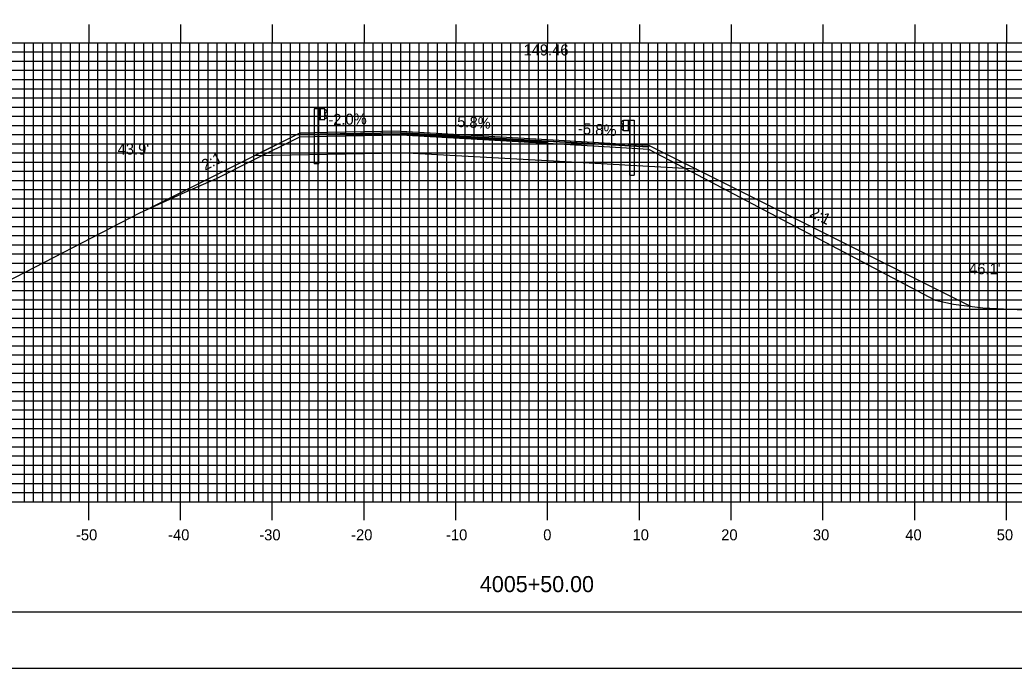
# Model space of a CAD drawing. Extents: x 851360 to 851703, y 364661 to 364881.
# Drawn here: x 851468.2 to 851576.6, y 364661.3 to 364731.9 of the extents above; entities that cross this region are included whole.
import ezdxf

# ---------------------------------------------------------------- set-up
doc = ezdxf.new("R2010")
doc.units = 0
for name, color, linetype in [('ANNOTATION', 7, 'Continuous'), ('BORDER', 7, 'Continuous'), ('D_Guardrail_Beam_Lt', 7, 'Continuous'), ('D_Guardrail_Beam_Rt', 7, 'Continuous'), ('D_Roadway_Centerline_Text', 7, 'Continuous'), ('D_Roadway_Edge_Shoulder', 7, 'Continuous'), ('D_Roadway_Edge_TW', 7, 'Continuous'), ('D_Roadway_Pavement', 7, 'Continuous'), ('D_Roadway_SlopeLines', 7, 'Continuous'), ('D_Roadway_SubGrade', 7, 'Continuous'), ('D_Text_Standard', 7, 'Continuous'), ('H_V ANNOTATION', 7, 'Continuous'), ('M_Roadway_Centerline', 7, 'Continuous'), ('MAJOR', 7, 'Continuous'), ('MINOR', 7, 'Continuous'), ('PLOT BOUNDARY', 7, 'Continuous'), ('S_Roadway_Centerline', 7, 'Continuous')]:
    doc.layers.add(name, color=color, linetype=linetype)

msp = doc.modelspace()

# ---------------------------------------------------------------- linework, layer by layer
at = {"layer": 'BORDER'}
msp.add_lwpolyline([(851376.13, 364667.37), (851696.13, 364667.37), (851696.13, 364877.37), (851376.13, 364877.37)], close=True, dxfattribs=at)
at = {"layer": 'D_Guardrail_Beam_Lt'}
for p, q in [((851500.3, 364722.19), (851500.3, 364716.19)), ((851500.77, 364722.19), (851500.3, 364722.19)), ((851501.46, 364722.19), (851500.77, 364722.19)), ((851500.77, 364722.19), (851500.77, 364721.02)), ((851500.83, 364722.19), (851500.83, 364721.02)), ((851500.94, 364722.19), (851500.94, 364721.02)), ((851501.46, 364721.02), (851501.46, 364722.19)), ((851501.46, 364722.1), (851501.53, 364722.09)), ((851501.55, 364722.08), (851501.69, 364721.98)), ((851500.77, 364721.02), (851501.46, 364721.02)), ((851500.79, 364716.19), (851500.79, 364721.02)), ((851501.46, 364721.64), (851501.46, 364721.57)), ((851501.53, 364721.12), (851501.46, 364721.1)), ((851501.69, 364721.84), (851501.5, 364721.7)), ((851501.5, 364721.5), (851501.69, 364721.37)), ((851501.69, 364721.22), (851501.55, 364721.12)), ((851500.79, 364716.19), (851500.3, 364716.19))]:
    msp.add_line(p, q, dxfattribs=at)
for centre, major_axis, start_param, end_param in [((851501.52, 364722.05), (0.0417, 0), 0.959931, 1.376053), ((851501.54, 364721.64), (-0.0789, 0), 5.323254, 6.283185), ((851501.54, 364721.57), (-0.0789, 0), 6.283185, 7.243116), ((851501.52, 364721.16), (0.0417, 0), 4.907132, 5.323254), ((851501.64, 364721.91), (0.0877, 0), 5.323254, 7.243116), ((851501.64, 364721.3), (0.0877, 0), 5.323254, 7.243116)]:
    msp.add_ellipse(centre, major_axis=major_axis, ratio=0.995501, start_param=start_param, end_param=end_param, dxfattribs=at)
at = {"layer": 'D_Guardrail_Beam_Rt'}
for p, q in [((851534, 364720.95), (851534.69, 364720.95)), ((851534, 364719.79), (851534, 364720.95)), ((851534.52, 364720.95), (851534.52, 364719.79)), ((851534.62, 364720.95), (851534.62, 364719.79)), ((851534.69, 364720.95), (851535.16, 364720.95)), ((851534.69, 364720.95), (851534.69, 364719.79)), ((851535.16, 364720.95), (851535.16, 364714.95)), ((851533.91, 364720.85), (851533.77, 364720.75)), ((851533.77, 364720.61), (851533.96, 364720.47)), ((851533.96, 364720.27), (851533.77, 364720.13)), ((851533.77, 364719.99), (851533.91, 364719.89)), ((851534, 364720.87), (851533.93, 364720.86)), ((851533.93, 364719.88), (851534, 364719.87)), ((851534, 364720.41), (851534, 364720.34)), ((851534.69, 364719.79), (851534, 364719.79)), ((851534.67, 364714.95), (851534.67, 364719.79)), ((851534.67, 364714.95), (851535.16, 364714.95))]:
    msp.add_line(p, q, dxfattribs=at)
for centre, major_axis, start_param, end_param in [((851533.82, 364720.68), (-0.0877, 0), 5.323254, 7.243116), ((851533.82, 364720.06), (-0.0877, 0), 5.323254, 7.243116), ((851533.93, 364720.82), (-0.0417, 0), 4.907132, 5.323254), ((851533.93, 364719.93), (-0.0417, 0), 0.959931, 1.376053), ((851533.92, 364720.41), (0.0789, 0), 0, 0.959931), ((851533.92, 364720.34), (0.0789, 0), 5.323254, 6.283185)]:
    msp.add_ellipse(centre, major_axis=major_axis, ratio=0.995501, start_param=start_param, end_param=end_param, dxfattribs=at)
at = {"layer": 'D_Roadway_Edge_Shoulder'}
for points in [[(851509.73, 364719.76), (851501.73, 364719.6), (851501.73, 364719.6), (851498.73, 364719.54), (851498.73, 364719.38), (851509.73, 364719.57)], [(851525.73, 364718.83), (851533.73, 364718.37), (851533.73, 364718.37), (851536.73, 364718.2), (851536.73, 364718.03), (851525.73, 364718.67)]]:
    msp.add_lwpolyline(points, close=True, dxfattribs=at)
at = {"layer": 'D_Roadway_Edge_TW'}
msp.add_lwpolyline([(851509.73, 364719.76), (851525.73, 364718.83), (851525.73, 364718.67), (851509.73, 364719.57)], close=True, dxfattribs=at)
at = {"layer": 'D_Roadway_Pavement'}
msp.add_lwpolyline([(851509.73, 364719.57), (851525.73, 364718.67), (851525.73, 364718.5), (851509.73, 364719.4)], close=True, dxfattribs=at)
for points in [[(851509.73, 364719.57), (851509.73, 364719.4)], [(851525.73, 364718.67), (851525.73, 364718.5)], [(851525.73, 364718.67), (851525.73, 364718.5)], [(851525.73, 364718.67), (851525.73, 364718.5)]]:
    msp.add_lwpolyline(points, dxfattribs=at)
at = {"layer": 'D_Roadway_SlopeLines'}
for points in [[(851498.73, 364719.54), (851481.79, 364711.07)], [(851536.73, 364718.2), (851571.79, 364700.67)]]:
    msp.add_lwpolyline(points, dxfattribs=at)
at = {"layer": 'D_Roadway_SubGrade'}
for points in [[(851509.73, 364719.4), (851509.73, 364719.57), (851498.73, 364719.38), (851498.73, 364719.54), (851493.81, 364717.08), (851509.73, 364717.4)], [(851509.73, 364719.4), (851525.73, 364718.5), (851525.73, 364716.5), (851509.73, 364717.4)], [(851525.73, 364718.5), (851525.73, 364718.67), (851536.73, 364718.03), (851536.73, 364718.2), (851541.94, 364715.59), (851525.73, 364716.5)]]:
    msp.add_lwpolyline(points, close=True, dxfattribs=at)
at = {"layer": 'MAJOR'}
for p, q in [((851475.73, 364731.37), (851475.73, 364729.37)), ((851485.73, 364731.37), (851485.73, 364729.37)), ((851495.73, 364731.37), (851495.73, 364729.37)), ((851505.73, 364731.37), (851505.73, 364729.37)), ((851515.73, 364731.37), (851515.73, 364729.37)), ((851525.73, 364731.37), (851525.73, 364729.37)), ((851535.73, 364731.37), (851535.73, 364729.37)), ((851545.73, 364731.37), (851545.73, 364729.37)), ((851555.73, 364731.37), (851555.73, 364729.37)), ((851565.73, 364731.37), (851565.73, 364729.37)), ((851575.73, 364731.37), (851575.73, 364729.37)), ((851385.73, 364729.37), (851665.73, 364729.37)), ((851385.73, 364729.37), (851665.73, 364729.37)), ((851475.73, 364679.37), (851475.73, 364729.37)), ((851485.73, 364679.37), (851485.73, 364729.37)), ((851495.73, 364679.37), (851495.73, 364729.37)), ((851505.73, 364679.37), (851505.73, 364729.37)), ((851515.73, 364679.37), (851515.73, 364729.37)), ((851525.73, 364679.37), (851525.73, 364729.37)), ((851535.73, 364679.37), (851535.73, 364729.37)), ((851545.73, 364679.37), (851545.73, 364729.37)), ((851555.73, 364679.37), (851555.73, 364729.37)), ((851565.73, 364679.37), (851565.73, 364729.37)), ((851575.73, 364679.37), (851575.73, 364729.37)), ((851385.73, 364724.37), (851665.73, 364724.37)), ((851385.73, 364719.37), (851665.73, 364719.37)), ((851385.73, 364714.37), (851665.73, 364714.37)), ((851385.73, 364709.37), (851665.73, 364709.37)), ((851385.73, 364704.37), (851665.73, 364704.37)), ((851385.73, 364699.37), (851665.73, 364699.37)), ((851385.73, 364694.37), (851665.73, 364694.37)), ((851385.73, 364689.37), (851665.73, 364689.37)), ((851385.73, 364684.37), (851665.73, 364684.37)), ((851385.73, 364679.37), (851665.73, 364679.37)), ((851385.73, 364679.37), (851665.73, 364679.37)), ((851475.73, 364677.37), (851475.73, 364679.37)), ((851485.73, 364677.37), (851485.73, 364679.37)), ((851495.73, 364677.37), (851495.73, 364679.37)), ((851505.73, 364677.37), (851505.73, 364679.37)), ((851515.73, 364677.37), (851515.73, 364679.37)), ((851525.73, 364677.37), (851525.73, 364679.37)), ((851535.73, 364677.37), (851535.73, 364679.37)), ((851545.73, 364677.37), (851545.73, 364679.37)), ((851555.73, 364677.37), (851555.73, 364679.37)), ((851565.73, 364677.37), (851565.73, 364679.37)), ((851575.73, 364677.37), (851575.73, 364679.37))]:
    msp.add_line(p, q, dxfattribs=at)
at = {"layer": 'MINOR'}
for p, q in [((851468.73, 364679.37), (851468.73, 364729.37)), ((851469.73, 364679.37), (851469.73, 364729.37)), ((851470.73, 364679.37), (851470.73, 364729.37)), ((851471.73, 364679.37), (851471.73, 364729.37)), ((851472.73, 364679.37), (851472.73, 364729.37)), ((851473.73, 364679.37), (851473.73, 364729.37)), ((851474.73, 364679.37), (851474.73, 364729.37)), ((851476.73, 364679.37), (851476.73, 364729.37)), ((851477.73, 364679.37), (851477.73, 364729.37)), ((851478.73, 364679.37), (851478.73, 364729.37)), ((851479.73, 364679.37), (851479.73, 364729.37)), ((851480.73, 364679.37), (851480.73, 364729.37)), ((851481.73, 364679.37), (851481.73, 364729.37)), ((851482.73, 364679.37), (851482.73, 364729.37)), ((851483.73, 364679.37), (851483.73, 364729.37)), ((851484.73, 364679.37), (851484.73, 364729.37)), ((851486.73, 364679.37), (851486.73, 364729.37)), ((851487.73, 364679.37), (851487.73, 364729.37)), ((851488.73, 364679.37), (851488.73, 364729.37)), ((851489.73, 364679.37), (851489.73, 364729.37)), ((851490.73, 364679.37), (851490.73, 364729.37)), ((851491.73, 364679.37), (851491.73, 364729.37)), ((851492.73, 364679.37), (851492.73, 364729.37)), ((851493.73, 364679.37), (851493.73, 364729.37)), ((851494.73, 364679.37), (851494.73, 364729.37)), ((851496.73, 364679.37), (851496.73, 364729.37)), ((851497.73, 364679.37), (851497.73, 364729.37)), ((851498.73, 364679.37), (851498.73, 364729.37)), ((851499.73, 364679.37), (851499.73, 364729.37)), ((851500.73, 364679.37), (851500.73, 364729.37)), ((851501.73, 364679.37), (851501.73, 364729.37)), ((851502.73, 364679.37), (851502.73, 364729.37)), ((851503.73, 364679.37), (851503.73, 364729.37)), ((851504.73, 364679.37), (851504.73, 364729.37)), ((851506.73, 364679.37), (851506.73, 364729.37)), ((851507.73, 364679.37), (851507.73, 364729.37)), ((851508.73, 364679.37), (851508.73, 364729.37)), ((851509.73, 364679.37), (851509.73, 364729.37)), ((851510.73, 364679.37), (851510.73, 364729.37)), ((851511.73, 364679.37), (851511.73, 364729.37)), ((851512.73, 364679.37), (851512.73, 364729.37)), ((851513.73, 364679.37), (851513.73, 364729.37)), ((851514.73, 364679.37), (851514.73, 364729.37)), ((851516.73, 364679.37), (851516.73, 364729.37)), ((851517.73, 364679.37), (851517.73, 364729.37)), ((851518.73, 364679.37), (851518.73, 364729.37)), ((851519.73, 364679.37), (851519.73, 364729.37)), ((851520.73, 364679.37), (851520.73, 364729.37)), ((851521.73, 364679.37), (851521.73, 364729.37)), ((851522.73, 364679.37), (851522.73, 364729.37)), ((851523.73, 364679.37), (851523.73, 364729.37)), ((851524.73, 364679.37), (851524.73, 364729.37)), ((851526.73, 364679.37), (851526.73, 364729.37)), ((851527.73, 364679.37), (851527.73, 364729.37)), ((851528.73, 364679.37), (851528.73, 364729.37)), ((851529.73, 364679.37), (851529.73, 364729.37)), ((851530.73, 364679.37), (851530.73, 364729.37)), ((851531.73, 364679.37), (851531.73, 364729.37)), ((851532.73, 364679.37), (851532.73, 364729.37)), ((851533.73, 364679.37), (851533.73, 364729.37)), ((851534.73, 364679.37), (851534.73, 364729.37)), ((851536.73, 364679.37), (851536.73, 364729.37)), ((851537.73, 364679.37), (851537.73, 364729.37)), ((851538.73, 364679.37), (851538.73, 364729.37)), ((851539.73, 364679.37), (851539.73, 364729.37)), ((851540.73, 364679.37), (851540.73, 364729.37)), ((851541.73, 364679.37), (851541.73, 364729.37)), ((851542.73, 364679.37), (851542.73, 364729.37)), ((851543.73, 364679.37), (851543.73, 364729.37)), ((851544.73, 364679.37), (851544.73, 364729.37)), ((851546.73, 364679.37), (851546.73, 364729.37)), ((851547.73, 364679.37), (851547.73, 364729.37)), ((851548.73, 364679.37), (851548.73, 364729.37)), ((851549.73, 364679.37), (851549.73, 364729.37)), ((851550.73, 364679.37), (851550.73, 364729.37)), ((851551.73, 364679.37), (851551.73, 364729.37)), ((851552.73, 364679.37), (851552.73, 364729.37)), ((851553.73, 364679.37), (851553.73, 364729.37)), ((851554.73, 364679.37), (851554.73, 364729.37)), ((851556.73, 364679.37), (851556.73, 364729.37)), ((851557.73, 364679.37), (851557.73, 364729.37)), ((851558.73, 364679.37), (851558.73, 364729.37)), ((851559.73, 364679.37), (851559.73, 364729.37)), ((851560.73, 364679.37), (851560.73, 364729.37)), ((851561.73, 364679.37), (851561.73, 364729.37)), ((851562.73, 364679.37), (851562.73, 364729.37)), ((851563.73, 364679.37), (851563.73, 364729.37)), ((851564.73, 364679.37), (851564.73, 364729.37)), ((851566.73, 364679.37), (851566.73, 364729.37)), ((851567.73, 364679.37), (851567.73, 364729.37)), ((851568.73, 364679.37), (851568.73, 364729.37)), ((851569.73, 364679.37), (851569.73, 364729.37)), ((851570.73, 364679.37), (851570.73, 364729.37)), ((851571.73, 364679.37), (851571.73, 364729.37)), ((851572.73, 364679.37), (851572.73, 364729.37)), ((851573.73, 364679.37), (851573.73, 364729.37)), ((851574.73, 364679.37), (851574.73, 364729.37)), ((851385.73, 364728.37), (851665.73, 364728.37)), ((851385.73, 364727.37), (851665.73, 364727.37)), ((851385.73, 364726.37), (851665.73, 364726.37)), ((851385.73, 364725.37), (851665.73, 364725.37)), ((851385.73, 364723.37), (851665.73, 364723.37)), ((851385.73, 364722.37), (851665.73, 364722.37)), ((851385.73, 364721.37), (851665.73, 364721.37)), ((851385.73, 364720.37), (851665.73, 364720.37)), ((851385.73, 364718.37), (851665.73, 364718.37)), ((851385.73, 364717.37), (851665.73, 364717.37)), ((851385.73, 364716.37), (851665.73, 364716.37)), ((851385.73, 364715.37), (851665.73, 364715.37)), ((851385.73, 364713.37), (851665.73, 364713.37)), ((851385.73, 364712.37), (851665.73, 364712.37)), ((851385.73, 364711.37), (851665.73, 364711.37)), ((851385.73, 364710.37), (851665.73, 364710.37)), ((851385.73, 364708.37), (851665.73, 364708.37)), ((851385.73, 364707.37), (851665.73, 364707.37)), ((851385.73, 364706.37), (851665.73, 364706.37)), ((851385.73, 364705.37), (851665.73, 364705.37)), ((851385.73, 364703.37), (851665.73, 364703.37)), ((851385.73, 364702.37), (851665.73, 364702.37)), ((851385.73, 364701.37), (851665.73, 364701.37)), ((851385.73, 364700.37), (851665.73, 364700.37)), ((851385.73, 364698.37), (851665.73, 364698.37)), ((851385.73, 364697.37), (851665.73, 364697.37)), ((851385.73, 364696.37), (851665.73, 364696.37)), ((851385.73, 364695.37), (851665.73, 364695.37)), ((851385.73, 364693.37), (851665.73, 364693.37)), ((851385.73, 364692.37), (851665.73, 364692.37)), ((851385.73, 364691.37), (851665.73, 364691.37)), ((851385.73, 364690.37), (851665.73, 364690.37)), ((851385.73, 364688.37), (851665.73, 364688.37)), ((851385.73, 364687.37), (851665.73, 364687.37)), ((851385.73, 364686.37), (851665.73, 364686.37)), ((851385.73, 364685.37), (851665.73, 364685.37)), ((851385.73, 364683.37), (851665.73, 364683.37)), ((851385.73, 364682.37), (851665.73, 364682.37)), ((851385.73, 364681.37), (851665.73, 364681.37)), ((851385.73, 364680.37), (851665.73, 364680.37))]:
    msp.add_line(p, q, dxfattribs=at)
at = {"layer": 'PLOT BOUNDARY'}
msp.add_lwpolyline([(851359.94, 364661.25), (851699.94, 364661.25), (851699.94, 364881.25), (851359.94, 364881.25)], close=True, dxfattribs=at)
at = {"layer": 'S_Roadway_Centerline'}
for points in [[(851489.65, 364714.59), (851493.52, 364716.53), (851498.73, 364719.13), (851501.73, 364719.19), (851509.73, 364719.35), (851525.73, 364718.42), (851533.73, 364717.96), (851536.73, 364717.78), (851542.07, 364714.97), (851567.97, 364701.34)], [(851385.73, 364688.72), (851388.91, 364688.93), (851400.08, 364689.25), (851405.67, 364689.62), (851416.25, 364690.29), (851430.53, 364691.53), (851433.06, 364691.66), (851448.42, 364694.67), (851448.62, 364694.71), (851464.4, 364702.17), (851465.67, 364702.79), (851481.28, 364710.84), (851486.23, 364713.08), (851489.65, 364714.59)], [(851567.97, 364701.34), (851569.96, 364700.89), (851573.14, 364700.5), (851579.13, 364700.2), (851581, 364700.11), (851596.8, 364701.03), (851598.31, 364701.08), (851613.16, 364702.25), (851613.88, 364702.3), (851614.56, 364702.29), (851630.83, 364702.08), (851631.08, 364702.08), (851640.65, 364703.15), (851647.46, 364703.83), (851659.92, 364704.09), (851663.96, 364704.22), (851665.73, 364704.47)]]:
    msp.add_lwpolyline(points, dxfattribs=at)

# ---------------------------------------------------------------- texts
at = {"layer": 'ANNOTATION'}
for s, rotation, p in [('-2.0%', 1.1458, (851501.84, 364720.4)), ('5.8%', 356.6806, (851515.84, 364720.21)), ('-5.8%', 356.6806, (851529.02, 364719.45)), ('2:1', 26.5651, (851488.4, 364715.42)), ('2:1', 333.4349, (851554.19, 364710.5))]:
    msp.add_text(s, height=1.2, rotation=rotation, dxfattribs=at).set_placement(p)
at = {"layer": 'D_Roadway_Centerline_Text'}
msp.add_text('149.46', height=1.2, dxfattribs=at).set_placement((851523.1, 364727.99))
at = {"layer": 'D_Text_Standard'}
for s, p in [("43.9'", (851478.88, 364717.2)), ("46.1'", (851571.65, 364704.16))]:
    msp.add_text(s, height=1.2, dxfattribs=at).set_placement(p)
at = {"layer": 'H_V ANNOTATION'}
for s, height, p in [('-50', 1.2, (851474.34, 364675.17)), ('-40', 1.2, (851484.38, 364675.17)), ('-30', 1.2, (851494.31, 364675.17)), ('-20', 1.2, (851504.32, 364675.17)), ('-10', 1.2, (851514.66, 364675.17)), ('0', 1.2, (851525.25, 364675.17)), ('10', 1.2, (851534.98, 364675.17)), ('20', 1.2, (851544.64, 364675.17)), ('30', 1.2, (851554.63, 364675.17)), ('40', 1.2, (851564.7, 364675.17)), ('50', 1.2, (851574.66, 364675.17)), ('4005+50.00', 1.75, (851518.35, 364669.53))]:
    msp.add_text(s, height=height, dxfattribs=at).set_placement(p)
at = {"layer": 'M_Roadway_Centerline'}
for s, p in [('C', (851513.98, 364717.63)), ('L', (851513.99, 364717.62))]:
    msp.add_text(s, height=0.0146, dxfattribs=at).set_placement(p)

doc.saveas('drawing.dxf')
